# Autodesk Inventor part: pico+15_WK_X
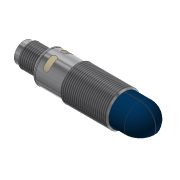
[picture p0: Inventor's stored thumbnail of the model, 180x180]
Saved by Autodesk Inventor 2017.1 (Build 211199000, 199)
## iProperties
Shininess: 20.0
Length Units: 11269
Angle Units: 11279
Time Units: 11290
Mass Units: 11283
Length Display Precision: 2
Angle Display Precision: 2
Part Number: pico+15_WK_X
Material: Nichtrostender Stahl - 440C
Document SubType Name: Modellieren
Description: Ipc-25 /CXX/M18
Checked By: Alves
Created: 2005-08
Designer: Ohle
Manufacturer: Standard
Standards Organization: Custom
Appearance: Aluminium - poliert
Density: 0.0
Volumn: 0.0
Area: 0.0
PropertySet Name: Model Information
Control State: 0
Master: False
Checked Out: False
BESTELLNUMMER: Ipc-25 /CXX/M18
ME: ST
Title: Ipc Sensoren
Author: Ohle
Comments: keine Bemerkung
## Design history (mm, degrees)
sketch "Skizze10"
  geometry: L1 (-43.018, 0)-(17.482, 0); L2 (-39.018, 6.5)-(-39.018, 7.25); L3 (-45.9, 8)-(-45.9, 8); L4 (-23.268, 9)-(0.232, 9); L5 (1.482, 0)-(-82.2, 0); L6 (-24.018, 8.25)-(-23.268, 9); L7 (0.982, 8.25)-(0.232, 9); L8 (-50.518, 6)-(-39.518, 6); L9 (-37.418, 8.25)-(-24.018, 8.25); L10 (-51.018, 4.5)-(-43.018, 4.5); L11 (-43.018, 0)-(-43.018, 4.5); L12 (-37.518, 8.25)-(-38.018, 8.25); L13 (-39.518, 6)-(-39.018, 6.5); L14 (-51.018, 5.5)-(-51.018, 4.5); L15 (-51.018, 5.5)-(-50.518, 6); L16 (-37.518, 8.25)-(-37.518, 8.15); L17 (-37.518, 8.15)-(-37.418, 8.15); L18 (-37.418, 8.15)-(-37.418, 8.25); L19 (0.982, 8.25)-(9.232, 8.25); L20 (17.482, 0)-(17.482, 0); A1 r 1 centre (-38.018, 7.25) between (-38.018, 8.25) and (-39.018, 7.25); A2 r 8.25 centre (9.232, 0) between (17.482, 0) and (9.232, 8.25); 4 further points
  constraints: 41 end point, 8 point on line, 5 parallel, 4 perpendicular, 4 point on circle, 4 tangent, 2 centre point, 2 horizontal, 1 collinear
  dimensions: "d171" = 4.5 distance between parallel lines of L10 L1; "d250" = 0.75 distance from line of L7.start L4; "d256" = 45 deg angle of L4 L6; "d257" = 8.25 distance between parallel lines of L5 L9; "d263" = 8.25 distance between parallel lines of L5 L12; "d266" = 12 distance from line of L2 L14.start; "d269" = 6 distance between parallel lines of L5 L8; "d289" = 135 deg angle of L7 L4; "d290" = 0.5 horizontal distance of L8.end L2.start; "d291" = 45 deg angle of L13 L8 (derived); "d293" = 0.5 horizontal distance of L14.start L8.start; "d294" = 45 deg angle of L15 L8 (derived); "d295" = 8 distance of L10.start L10.end; "d296" = 1.5 distance of L12.start point (-39.018, 8.25); "d297" = 0.1 distance of L16.end L17.end; "d298" = 8.15 distance between parallel lines of L17 L1; "d299" = 15 distance from line of L6.start L2; "d300" = 1 radius of A1; "d338" = 8.25 radius of A2; "d339" = 16.5 horizontal distance of L20.end L7.start; "d340" = 8.25 distance between parallel lines of L1 L19 (derived); "d365" = 25 distance of L7.start L6.start
revolve "Grundkörper pico+" sketch "Skizze10" stored, may be unused: angle "d168" = 90 deg
feature "Gewinde M12" dims "d174" = 10, "d175" = 0
feature "Gewinde M 18" dims "d179" = 10, "d180" = 0
workplane "Arbeitsebene1"
workplane "Arbeitsebene2"
sketch "Skizze13"
  geometry: L1 (-3.409, -3.409)-(3.61, 3.61); L2 (-3.439, 3.439)-(4.105, -4.105); L3 (-12.6, 0)-(12.6, 0) reference; C1 r 0.5 at (2.121, -2.121); C2 r 0.5 at (2.121, 2.121); C3 r 0.5 at (-2.121, 2.121); C4 r 0.5 at (-2.121, -2.121); C5 r 4.5 at (0, 0) reference; C6 r 0.5 at (0, 0); A1 r 3 centre (0, 0) between (-2.121, 2.121) and (2.121, 2.121); 2 further points
  constraints: 6 centre point, 6 point on line, 4 coincident, 4 end point, 4 equal radius, 4 point on circle, 1 horizontal alignment, 1 perpendicular
  dimensions: "d208" = 1 diameter of C3; "d209" = 6 diameter of A1
extrude "Pole" join sketch "Skizze13" distance "d212" = 7; taper "d213" = 0 deg
fillet "Rundung Pole" dims "d214" = 0.5
sketch "Skizze14"
  geometry: C1 r 0.5 at (0, -4.5); A1 r 4.5 centre (0, 0) between (4.435, -0.762) and (4.435, 0.762); A2 r 4.5 centre (0, 0) between (0, 4.5) and (0.499, 4.472) reference; A3 r 0.5 centre (0, 4.5) between (-0.499, 4.472) and (0.499, 4.472); 3 further points
  constraints: 9 point on circle, 3 centre point, 3 coincident, 1 horizontal alignment, 1 vertical alignment
  dimensions: "d215" = 9 diameter of A1; "d280" = 1 diameter of A3; "d330" = 1 diameter of C1
extrude "Verdrehsicherung" join sketch "Skizze14" distance "d217" = 7; taper "d218" = 0 deg
sketch "Skizze18"
  geometry: C1 r 7.25 at (0, 0) reference; C2 r 1 at (-8.15, 0)
  constraints: 1 centre point, 1 horizontal alignment
  dimensions: "d328" = 2 diameter of C2; "d329" = 8.15 distance of C1.centre C2.centre
extrude "Bohrung Ausrichtung" cut sketch "Skizze18" distance "d316" = 0.75; taper "d317" = 0 deg
workplane "Arbeitsebene4"
sketch "Skizze19"
  geometry: L1 (-39.018, 0)-(-30.18, 0); L2 (-34.718, -7.5)-(-34.718, -3); L3 (-31.718, -7.5)-(-31.718, -3); L4 (-31.718, 3)-(-31.718, 7.5); L5 (-34.718, 3)-(-34.718, 7.5); A1 r 1.5 centre (-33.218, 3) between (-31.718, 3) and (-34.718, 3); A2 r 1.5 centre (-33.218, -3) between (-34.718, -3) and (-31.718, -3); A3 r 1.5 centre (-33.218, 7.5) between (-31.718, 7.5) and (-34.718, 7.5); A4 r 1.5 centre (-33.218, -7.5) between (-34.718, -7.5) and (-31.718, -7.5); 4 further points; 1 other entity
  constraints: 10 end point, 8 point on circle, 8 tangent, 4 centre point, 3 equal radius, 2 vertical alignment, 1 horizontal, 2 other
  dimensions: "d319" = 3 diameter of A2; "d320" = 6 distance of A2.centre A1.centre; "d321" = 4.5 distance of A1.centre A3.centre; "d322" = 4.5 distance of A4.centre A2.centre; "d323" = 3 distance from line of A2.centre L1; "d324" = 5.8 dimension on A1.centre; "d325" = 5.8 dimension on A2.centre
feature "Prägen LED-Fenster" sketch "Skizze19" dims "d326" = 0.01, "d327" = 0
workplane "Arbeitsebene5"
sketch "Skizze20"
  geometry: L1 (9.232, -8.25)-(9.232, 8.25) reference; L2 (0.982, -8.25)-(0.982, 8.25) reference; L3 (9.232, -8.25)-(9.232, 8.25) reference; L4 (1.482, -8.25)-(18.508, -8.25); L5 (18.508, -8.25)-(18.508, 8.25); L6 (18.508, 8.25)-(1.482, 8.25); L7 (1.482, 8.25)-(1.482, -8.25)
  constraints: 8 end point, 2 parallel, 1 horizontal, 1 perpendicular
  dimensions: "d342" = 0.5 distance between parallel lines of L7 L2
extrude "USW-Fläche Winkelkopf" cut sketch "Skizze20" distance "d343" = 4.8; taper "d344" = 0 deg
sketch "Skizze21"
  geometry: C1 r 7 at (-9.232, 0); A1 r 7.494 centre (-9.232, 0) between (-9.232, 7.494) and (-9.232, -7.494) reference
  constraints: 1 centre point, 1 coincident
  dimensions: "d345" = 14 diameter of C1
extrude "Extrusion6" cut sketch "Skizze21" distance "d346" = 0.01; taper "d347" = 0 deg
sketch "Skizze22"
  geometry: C1 r 7 at (0, 0) reference; C2 r 2.5 at (0, 0)
  constraints: 1 centre point, 1 coincident
  dimensions: "d348" = 5 diameter of C2
extrude "Extrusion7" join sketch "Skizze22" distance "d349" = 0.01; taper "d350" = 0 deg
sketch "Skizze28"
  geometry: L1 (-0.982, 8.25)-(-9.232, 8.25) reference; L2 (-0.982, 8.25)-(-0.982, -8.25) reference; L3 (-9.232, -3.45)-(-16.726, -3.45) reference; L4 (-9.232, 8.15)-(-0.982, 8.15); A1 r 8.25 centre (-9.232, 0) between (-9.232, 8.25) and (-16.726, -3.45) reference; A2 r 8.15 centre (-9.232, 0) between (-9.232, 8.15) and (-16.616, -3.45)
  constraints: 2 end point, 2 point on circle, 2 point on line, 1 centre point, 1 coincident, 1 perpendicular, 1 tangent
  dimensions: "d362" = 0.1 radial gap between concentric circles of A2 A1
extrude "Extrusion8" cut sketch "Skizze28" stored distance "d363" = 0.3; taper "d364" = 0 deg
sketch "Skizze29"
  geometry: C1 r 5.5 at (0, 0); C2 r 4.5 at (0, 0); C3 r 4.15 at (0, 0); C4 r 5.25 at (0, 0); 2 further points
  constraints: 4 centre point
  dimensions: "d366" = 8.3 diameter of C3; "d367" = 10.5 diameter of C4
extrude "Extrusion9" join sketch "Skizze29" stored distance "d368" = 1; taper "d369" = 0 deg
sketch "Skizze30"
  geometry: C1 r 5.25 at (0, 0) reference; C2 r 8.312 at (0, 0); 1 further point
  constraints: 1 centre point
extrude "Extrusion10" cut sketch "Skizze30" distance "d370" = 2.6; taper "d371" = 0 deg
chamfer "Fase2" distance "d372" = 0.75; stored, may be unused: second distance "d373" = 2, angle "d374" = 30 deg
node "Volumenkörper1"
node "Volumenkörper"
node "Flächenkörper"
node "Projizierte Kontur2"
node "Projizierte Kontur3"
other parameters: "d10" = 14, "d73" = -35, "d130" = 0.2, "d207" = -95.5, "d318" = 8.25, "d341" = -8.25
